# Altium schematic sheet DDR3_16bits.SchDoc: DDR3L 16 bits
size A4; Date: 30-MAR-2016; Author: F.L; CompanyName: STMicroelectronics; Organization: MCD/APPLI/HW; Address1: 12, Rue Jules HOROWITZ; Address2: 38019 Grenoble; Address3: FRANCE; DocumentNumber: MB1272; Revision: A-01; SheetNumber: 11; SheetTotal: 15; Project: STM32MP15-DISCO PI; PageSetup: Record=PageOptions¦CenterHorizontal=True¦CenterVertical=True¦PrintScale=1.39¦XCorrection=1.00¦YCorrection=1.00¦PrintKind=1¦BorderSize=5000000¦LeftOffset=0¦BottomOffset=0¦Orientation=2¦PaperLength=1000¦PaperWidth=1000¦Scale=100¦PaperSource=15¦PrintQuality=600¦MediaType=1¦DitherType=10¦PrintScaleMode=1¦PaperKind=A3¦PaperIndex=8
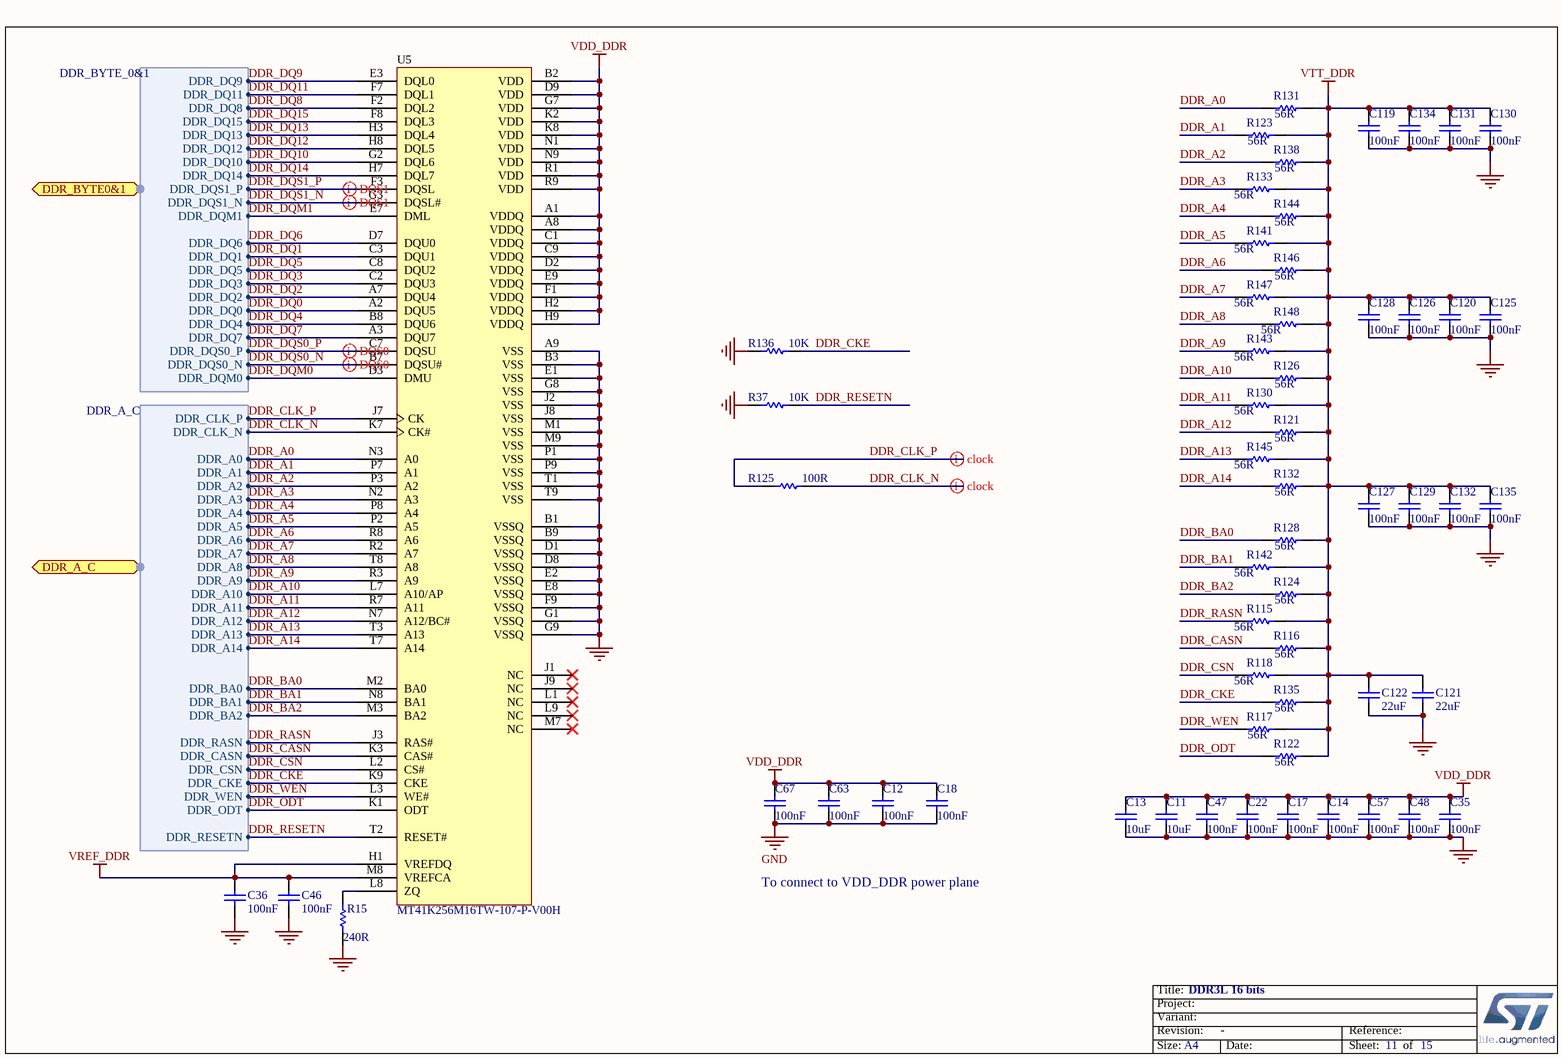
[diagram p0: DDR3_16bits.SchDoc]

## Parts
C11  value 10uF  [C0603]  (hidden comment: Capacitor)
C12  value 100nF  [C0402]  (hidden comment: Capacitor)
C13  value 10uF  [C0603]  (hidden comment: Capacitor)
C14  value 100nF  [C0402]
C17  value 100nF  [C0402]
C18  value 100nF  [C0402]  (hidden comment: Capacitor)
C22  value 100nF  [C0402]
C35  value 100nF  [C0402]
C36  value 100nF  [C0402]
C46  value 100nF  [C0402]
C47  value 100nF  [C0402]
C48  value 100nF  [C0402]
C57  value 100nF  [C0402]
C63  value 100nF  [C0402]  (hidden comment: Capacitor)
C67  value 100nF  [C0402]  (hidden comment: Capacitor)
C119  value 100nF  [C0402]
C120  value 100nF  [C0402]
C121  value 22uF  [C0603]
C122  value 22uF  [C0603]
C125  value 100nF  [C0402]
C126  value 100nF  [C0402]
C127  value 100nF  [C0402]
C128  value 100nF  [C0402]
C129  value 100nF  [C0402]
C130  value 100nF  [C0402]
C131  value 100nF  [C0402]
C132  value 100nF  [C0402]
C134  value 100nF  [C0402]
C135  value 100nF  [C0402]
R15  value 240R  [R0402]
R37  value 10K  [R0402]  (hidden comment: Resistor)
R115  value 56R  [R0402]
R116  value 56R  [R0402]
R117  value 56R  [R0402]
R118  value 56R  [R0402]
R121  value 56R  [R0402]
R122  value 56R  [R0402]
R123  value 56R  [R0402]
R124  value 56R  [R0402]
R125  value 100R  [R0402]  (hidden comment: Resistor)
R126  value 56R  [R0402]
R128  value 56R  [R0402]
R130  value 56R  [R0402]
R131  value 56R  [R0402]
R132  value 56R  [R0402]
R133  value 56R  [R0402]
R135  value 56R  [R0402]
R136  value 10K  [R0402]  (hidden comment: Resistor)
R138  value 56R  [R0402]
R141  value 56R  [R0402]
R142  value 56R  [R0402]
R143  value 56R  [R0402]
R144  value 56R  [R0402]
R145  value 56R  [R0402]
R146  value 56R  [R0402]
R147  value 56R  [R0402]
R148  value 56R  [R0402]
U5  value MT41K256M16TW-107-P-V00H  [ICC_FBGA96_8X14_P080]  (hidden comment: MT41K256M16TW-107:P - V00H)

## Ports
DDR_A_C (harness DDR_A_C), DDR_BYTE0&1 (harness DDR_BYTE_0&1)

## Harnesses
DDR_A_C: DDR_A4, DDR_A0, DDR_A2, DDR_A1, DDR_A6, DDR_A3, DDR_A5, DDR_A7, DDR_A8, DDR_A9, DDR_A14, DDR_A10, DDR_A12, DDR_A11, DDR_BA0, DDR_A13, DDR_BA1, DDR_BA2, DDR_RASN, DDR_CASN, DDR_CSN, DDR_CKE, DDR_WEN, DDR_ODT, DDR_CLK_P, DDR_CLK_N, DDR_RESETN
DDR_BYTE_0&1: DDR_DQ13, DDR_DQ9, DDR_DQ8, DDR_DQ11, DDR_DQ10, DDR_DQ15, DDR_DQ12, DDR_DQ14, DDR_DQS1_P, DDR_DQS1_N, DDR_DQ5, DDR_DQM1, DDR_DQ6, DDR_DQ2, DDR_DQ1, DDR_DQ3, DDR_DQ0, DDR_DQ4, DDR_DQ7, DDR_DQS0_P, DDR_DQS0_N, DDR_DQM0

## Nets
GND: C11.1 C12.1 C13.1 C14.2 C17.2 C18.1 C22.2 C35.2 C36.2 C46.2 C47.2 C48.2 C57.2 C63.1 C67.1 C119.2 C120.2 C121.1 C122.1 C125.2 C126.2 C127.2 C128.2 C129.2 C130.2 C131.2 C132.2 C134.2 C135.2 R15.1 R37.1 R136.1 U5.A9(VSS) U5.B1(VSSQ) U5.B3(VSS) U5.B9(VSSQ) U5.D1(VSSQ) U5.D8(VSSQ) U5.E1(VSS) U5.E2(VSSQ) U5.E8(VSSQ) U5.F9(VSSQ) U5.G1(VSSQ) U5.G8(VSS) U5.G9(VSSQ) U5.J2(VSS) U5.J8(VSS) U5.M1(VSS) U5.M9(VSS) U5.P1(VSS) U5.P9(VSS) U5.T1(VSS) U5.T9(VSS)
VDD_DDR: C11.2 C12.2 C13.2 C14.1 C17.1 C18.2 C22.1 C35.1 C47.1 C48.1 C57.1 C63.2 C67.2 U5.A1(VDDQ) U5.A8(VDDQ) U5.B2(VDD) U5.C1(VDDQ) U5.C9(VDDQ) U5.D2(VDDQ) U5.D9(VDD) U5.E9(VDDQ) U5.F1(VDDQ) U5.G7(VDD) U5.H2(VDDQ) U5.H9(VDDQ) U5.K2(VDD) U5.K8(VDD) U5.N1(VDD) U5.N9(VDD) U5.R1(VDD) U5.R9(VDD)
VREF_DDR: C36.1 C46.1 U5.H1(VREFDQ) U5.M8(VREFCA)
VTT_DDR: C119.1 C120.1 C121.2 C122.2 C125.1 C126.1 C127.1 C128.1 C129.1 C130.1 C131.1 C132.1 C134.1 C135.1 R115.2 R116.2 R117.2 R118.2 R121.2 R122.2 R123.2 R124.2 R126.2 R128.2 R130.2 R131.2 R132.2 R133.2 R135.2 R138.2 R141.2 R142.2 R143.2 R144.2 R145.2 R146.2 R147.2 R148.2
DDR_A0: R131.1 U5.N3(A0) ; port DDR_A_C.DDR_A0
DDR_A1: R123.1 U5.P7(A1) ; port DDR_A_C.DDR_A1
DDR_A2: R138.1 U5.P3(A2) ; port DDR_A_C.DDR_A2
DDR_A3: R133.1 U5.N2(A3) ; port DDR_A_C.DDR_A3
DDR_A4: R144.1 U5.P8(A4) ; port DDR_A_C.DDR_A4
DDR_A5: R141.1 U5.P2(A5) ; port DDR_A_C.DDR_A5
DDR_A6: R146.1 U5.R8(A6) ; port DDR_A_C.DDR_A6
DDR_A7: R147.1 U5.R2(A7) ; port DDR_A_C.DDR_A7
DDR_A8: R148.1 U5.T8(A8) ; port DDR_A_C.DDR_A8
DDR_A9: R143.1 U5.R3(A9) ; port DDR_A_C.DDR_A9
DDR_A10: R126.1 U5.L7(A10/AP) ; port DDR_A_C.DDR_A10
DDR_A11: R130.1 U5.R7(A11) ; port DDR_A_C.DDR_A11
DDR_A12: R121.1 U5.N7(A12/BC#) ; port DDR_A_C.DDR_A12
DDR_A13: R145.1 U5.T3(A13) ; port DDR_A_C.DDR_A13
DDR_A14: R132.1 U5.T7(A14) ; port DDR_A_C.DDR_A14
DDR_BA0: R128.1 U5.M2(BA0) ; port DDR_A_C.DDR_BA0
DDR_BA1: R142.1 U5.N8(BA1) ; port DDR_A_C.DDR_BA1
DDR_BA2: R124.1 U5.M3(BA2) ; port DDR_A_C.DDR_BA2
DDR_CASN: R116.1 U5.K3(CAS#) ; port DDR_A_C.DDR_CASN
DDR_CKE: R135.1 R136.2 U5.K9(CKE) ; port DDR_A_C.DDR_CKE
DDR_CLK_N: R125.2 U5.K7(CK#) ; port DDR_A_C.DDR_CLK_N
DDR_CLK_P: R125.1 U5.J7(CK) ; port DDR_A_C.DDR_CLK_P
DDR_CSN: R118.1 U5.L2(CS#) ; port DDR_A_C.DDR_CSN
DDR_DQ0: U5.A2(DQU5) ; port DDR_BYTE0&1.DDR_DQ0
DDR_DQ1: U5.C3(DQU1) ; port DDR_BYTE0&1.DDR_DQ1
DDR_DQ2: U5.A7(DQU4) ; port DDR_BYTE0&1.DDR_DQ2
DDR_DQ3: U5.C2(DQU3) ; port DDR_BYTE0&1.DDR_DQ3
DDR_DQ4: U5.B8(DQU6) ; port DDR_BYTE0&1.DDR_DQ4
DDR_DQ5: U5.C8(DQU2) ; port DDR_BYTE0&1.DDR_DQ5
DDR_DQ6: U5.D7(DQU0) ; port DDR_BYTE0&1.DDR_DQ6
DDR_DQ7: U5.A3(DQU7) ; port DDR_BYTE0&1.DDR_DQ7
DDR_DQ8: U5.F2(DQL2) ; port DDR_BYTE0&1.DDR_DQ8
DDR_DQ9: U5.E3(DQL0) ; port DDR_BYTE0&1.DDR_DQ9
DDR_DQ10: U5.G2(DQL6) ; port DDR_BYTE0&1.DDR_DQ10
DDR_DQ11: U5.F7(DQL1) ; port DDR_BYTE0&1.DDR_DQ11
DDR_DQ12: U5.H8(DQL5) ; port DDR_BYTE0&1.DDR_DQ12
DDR_DQ13: U5.H3(DQL4) ; port DDR_BYTE0&1.DDR_DQ13
DDR_DQ14: U5.H7(DQL7) ; port DDR_BYTE0&1.DDR_DQ14
DDR_DQ15: U5.F8(DQL3) ; port DDR_BYTE0&1.DDR_DQ15
DDR_DQM0: U5.D3(DMU) ; port DDR_BYTE0&1.DDR_DQM0
DDR_DQM1: U5.E7(DML) ; port DDR_BYTE0&1.DDR_DQM1
DDR_DQS0_N: U5.B7(DQSU#) ; port DDR_BYTE0&1.DDR_DQS0_N
DDR_DQS0_P: U5.C7(DQSU) ; port DDR_BYTE0&1.DDR_DQS0_P
DDR_DQS1_N: U5.G3(DQSL#) ; port DDR_BYTE0&1.DDR_DQS1_N
DDR_DQS1_P: U5.F3(DQSL) ; port DDR_BYTE0&1.DDR_DQS1_P
DDR_ODT: R122.1 U5.K1(ODT) ; port DDR_A_C.DDR_ODT
DDR_RASN: R115.1 U5.J3(RAS#) ; port DDR_A_C.DDR_RASN
DDR_RESETN: R37.2 U5.T2(RESET#) ; port DDR_A_C.DDR_RESETN
DDR_WEN: R117.1 U5.L3(WE#) ; port DDR_A_C.DDR_WEN
NetR15_2: R15.2 U5.L8(ZQ)

Not connected (* = marked no-connect by the designer): U5 J1(NC)* J9(NC)* L1(NC)* L9(NC)* M7(NC)*

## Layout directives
differential pair: DDR_CLK_N, DDR_CLK_P, DDR_DQS0_N, DDR_DQS0_P, DDR_DQS1_N, DDR_DQS1_P

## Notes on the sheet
- To connect to VDD_DDR power plane

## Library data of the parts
C11 C13 = MCD-00099: Capacitor, MLCC, 10uF, 10V, X5R, 10%, 0603, T=0,8mm; Manufacturer_Part_Number: GRM188R61A106KE69D; Manufacturer: MURATA; ECCN_US: EAR99; ECCN_EU: NEC; Provided_By: SUBCO; Initial_Board_Reference: MB1262
C12 C18 C63 C67 = MCD-00006: Capacitor, MLCC, 100nF, 16V, X7R, 10%, 0402, T=0.5mm; Manufacturer_Part_Number: CC0402KRX7R7BB104; Manufacturer: YAGEO; Alternate_Manufacturer: MURATA; Alternate_Manufacturer_Part_Number: GCM155R71C104KA55D; Provided_By: SUBCO; Initial_Board_Reference: MB1274
C14 C17 C22 C35 C36 C46-C48 C57 C119 C120 C125-C132 C134 C135 = MCD-00006: Capacitor,100nF,16V,X7R,10%,0402; Manufacturer_Part_Number: CC0402KRX7R7BB104; Manufacturer: YAGEO; Alternate_Manufacturer: MURATA; Alternate_Manufacturer_Part_Number: GCM155R71C104KA55D; Provided_By: SUBCO; Initial_Board_Reference: mb1274
C121 C122 = MCD-00100: Capacitor, MLCC, 22uF, 6V3, X5R, 20%, 0603, T=0,8mm; Manufacturer_Part_Number: GRM188R60J226MEA0J; Manufacturer: MURATA; ECCN_US: EAR99; ECCN_EU: NEC; Provided_By: SUBCO; Initial_Board_Reference: mb1262
R15 = MCD-00120: Resistor,240R,0402,1%,1/16W; Manufacturer_Part_Number: RC0402FR-07240RL; Manufacturer: YAGEO; Provided_By: SUBCO; Initial_Board_Reference: mb1262
R37 R136 = MCD-00053: Resistor,10K,0402,1%,1/16W; Manufacturer_Part_Number: RC0402FR-0710KL; Manufacturer: YAGEO; Provided_By: SUBCO; Initial_Board_Reference: MB1274
R115-R118 R121-R124 R126 R128 R130-R133 R135 R138 R141-R148 = MCD-00118: Resistor,56R,0402,1%,1/16W; Manufacturer_Part_Number: RC0402FR-0756RL; Manufacturer: YAGEO; Provided_By: SUBCO; Initial_Board_Reference: mb1262
R125 = MCD-00067: Resistor,100R,0402,1%,1/16W; Manufacturer_Part_Number: RC0402FR-07100RL; Manufacturer: YAGEO; Provided_By: SUBCO; Initial_Board_Reference: MB1274
U5 = MCD-00207: Memory,DDR3L,4Gb,256Mbx16,1866MT/s,1V35,FBGA96; Part_Type: IC; Manufacturer: MICRON; Provided_By: SUBCO; Initial_Board_Reference: MB1263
